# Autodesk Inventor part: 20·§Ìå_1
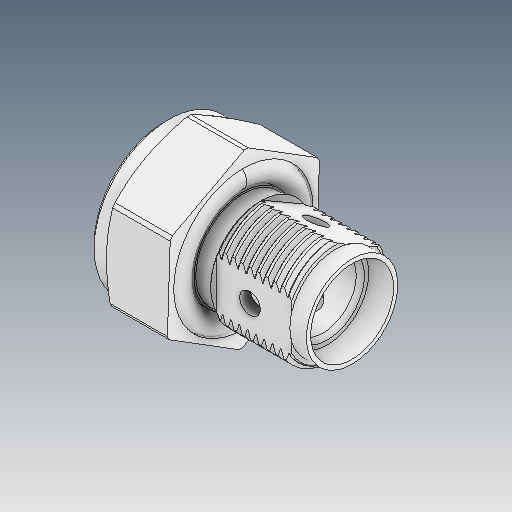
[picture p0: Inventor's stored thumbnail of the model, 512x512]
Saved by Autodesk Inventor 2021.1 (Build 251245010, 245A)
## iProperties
Created: 2021-05
Part Number: 20·§Ìå_1
Material: Ogólny
Document SubType Name: Modeling
Designer: user
Density: 1 g/cm^3
Appearance: Domyślna
Author: user
Revision Number: ÈÎºÎ
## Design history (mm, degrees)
feature "ÊäÈë1"
feature "ÊäÈë2"
node "Bryła1"
node "Bryła2"
